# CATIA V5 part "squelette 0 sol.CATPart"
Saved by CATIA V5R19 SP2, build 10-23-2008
Part number: squelette batis 0
Publications: "Ligne de contact", "Sol"
Bounding box of the stored display mesh (mm): x -100 to 100, y 0 to 0, z 0 to 0
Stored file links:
  G:\EU_thinkMotion\CFAO_2010\MMS_groupe3\MMS_groupe3\A reprendre\mmugnier\Systeme_Cric_Y\Systeme_Cric_Y\squelette 0 sol.CATPart
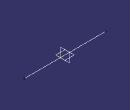
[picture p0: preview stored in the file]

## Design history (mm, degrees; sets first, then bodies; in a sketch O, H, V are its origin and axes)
Set1
  Line1 "Ligne de contact": type Normal, RefPoint {point type Coord, X 0, Y 0, Z 0}, RefSkin yz-plane, Start -100, End 100
Body1 (main body)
